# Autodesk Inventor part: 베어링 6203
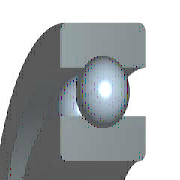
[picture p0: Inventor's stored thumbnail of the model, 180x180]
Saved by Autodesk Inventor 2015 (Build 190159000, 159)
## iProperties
IsCustomPart: 0
Created: 2016-04
Part Number: 베어링 6203
Material: 강철, 연강
Description: 깊은 그루브 볼 베어링
Document SubType Name: Modeling
Standard: KS B 2023
Designer: mdu
Standards Organization: KS
Language: ko-KR
Size Designation: 6203 - 17 x 40 x 12
Categories: <MemberInstance><Categories><Category DisplayName="샤프트 부품" InternalName="7f7aeb1f-a693-4053-b835-cee3144e0d98" Mnemonic="SHFT"><Category DisplayName="베어링" Inter
Density: 7.86 g/cm^3
Mass: 64.9809 g
Surface Area: 64.3582 cm^2
Volume: 8.26729 cm^3
Appearance: 노란색
Author: mdu
Revision Number: 1
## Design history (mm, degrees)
sketch "스케치" dims "d0" = 5.98 (= -0.26 x WD + 0.26 x BD)
  geometry: L1 (3.01, 14.25)-(8.99, 14.25); L2 (6, 14.25)-(6, 11.26); L3 (6, 14.25)-(6, 17.24); L4 (3.778, 12.249)-(0, 12.249); L5 (0, 8.5)-(12, 8.5); L6 (3.778, 16.251)-(0, 16.251); L7 (0, 20)-(12, 20); L8 (12, 8.5)-(12, 12.249); L9 (8.222, 12.249)-(12, 12.249); L10 (8.222, 16.251)-(12, 16.251); L11 (12, 20)-(12, 16.251); L12 (-1.4, 0)-(8.4, 0) reference; L13 (0, -0.3)-(0, 5.3) reference
  constraints: 22 end point, 4 point on line, 2 collinear, 2 perpendicular, 2 symmetric about line, 1 midpoint, 1 parallel, 14 other
  dimensions: "d9" = 17 diameter of L5 L12 (= WD); "d11" = 40 diameter of L7 L12 (= BD); "d12" = 12 distance between parallel lines of L8 L13 (= KB); "d13" = 24.498 diameter of L9 L12 (= 0.326 x BD + 0.674 x WD)
revolve "본체" stored, may be unused: angle "d6" = 90 deg
revolve "볼" stored, may be unused: angle "d7" = 90 deg
pattern_circular "IDS_ARRAYBALL[SIMPL:T]" dims angle "d3" = 360 deg
body "Solid1"
fillet "모깎기1" dims "d1" = 0.6 (= KRS)
other parameters: "WD" = 17 [user parameter; used in 5 equation terms], "BD" = 40 [user parameter; used in 5 equation terms], "KB" = 12 [user parameter; used in 1 equation term], "KRS" = 0.6 [user parameter; used in 1 equation term], "d4" = 0, "d5" = 0, "d8" = 0, "d14" = 0, "d15" = 0, "BBA" = 0 [user parameter], "BC0" = 4750000 [user parameter], "BC" = 9560000 [user parameter], "WR" = 8.5 (= 0.5 x WD) [user parameter]
